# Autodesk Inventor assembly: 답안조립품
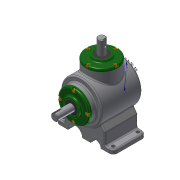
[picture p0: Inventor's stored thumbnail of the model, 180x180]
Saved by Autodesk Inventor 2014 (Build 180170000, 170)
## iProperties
Created: 2018-08
Part Number: 답안조립품
Document SubType Name: Assembly
Designer: 601-24
Author: 601-24
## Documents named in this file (14)
- C:\Users\601-24\Desktop\480808V1006\답안조립품.iam
- C:\Users\601-24\Desktop\480808V1006\본체.ipt
- C:\Users\601-24\Desktop\480808V1006\메인 베벨기어.ipt
- C:\Users\601-24\Desktop\480808V1006\메인 축.ipt
- 메인 축.ipt
- C:\Users\601-24\Desktop\480808V1006\베어링 6203.ipt
- C:\Users\601-24\Desktop\480808V1006\볼트 M4.ipt
- C:\Users\601-24\Desktop\480808V1006\서브 베벨기어.ipt
- C:\Users\601-24\Desktop\480808V1006\서브 축.ipt
- 서브 축.ipt
- C:\Users\601-24\Desktop\480808V1006\오일실 17 32 8.ipt
- C:\Users\601-24\Desktop\480808V1006\커버.ipt
- C:\Users\601-24\Desktop\480808V1006\키 4x4.ipt
- C:\Users\601-24\Desktop\480808V1006\키 5x5.ipt
## Named parameters: d4_d2 = 0, d5_d3 = 0, d6_d0 = 0, d7_d1 = 0
